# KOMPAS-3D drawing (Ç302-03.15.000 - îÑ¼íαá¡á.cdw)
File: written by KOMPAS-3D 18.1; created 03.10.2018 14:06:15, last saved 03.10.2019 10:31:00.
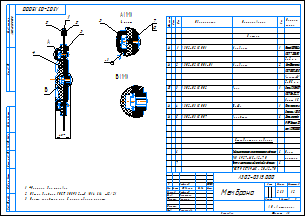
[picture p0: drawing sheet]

Sheet 1: A3, landscape

Document properties: Автор: Милов; Полное имя файла: D:\Мембранные насосы\Мембранный электропривод\А302-00.00.000 - ASTRA-302 (МЭ200)\Чертежи Полипропилен\А302-03.15.000 - Мембрана.cdw; Масса: 2.62614

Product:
- Part/product: (unnamed)
  - Component: Болт с шестигранной головкой с фланцем  / ГОСТ Р 55739-М5 x 20-A2-70  | pos. 7  | Раздел спецификации: Стандартные изделия
  - Component: Гайка шестигранная самостопорящаяся с фланцем / DIN 6927-M5-A2-70  | pos. 6  | Раздел спецификации: Стандартные изделия; Примечание: Нерж. / насечки
  - Component: Заглушка  | designation А302-03.15.007  | pos. 5  | Раздел спецификации: Детали; Форматы листов документа: А4; Примечание: Деталь заготовка  / FV PPR Заглушка @2~20 / арт. AA229020000
  - Component: Шайба  | designation А302-03.15.003  | pos. 4  | Раздел спецификации: Детали; Форматы листов документа: А4; Примечание: Полипропилен / Стержень @2~300
  - Component: Упор  | designation А302-02.15.002  | pos. 3  | Раздел спецификации: Детали; Форматы листов документа: А3; Примечание: Сталь 12Х18Н10Т / ГОСТ 5632-72 / Лист 15
  - Component: Мембрана  | designation А302-02.15.001-01  | pos. 2  | Раздел спецификации: Детали; Форматы листов документа: А4; Примечание: Лист Фторопласт-4 /  ГОСТ 10007-80 Е / "каленный" / S=0,5 мм
  - Component: Мембрана  | designation А302-02.15.001  | pos. 1  | Раздел спецификации: Детали; Форматы листов документа: А4; Примечание: Пластина ІФ-IІ ТМКЩ-C-4 / ГОСТ 7338-90 / S=2 мм

Title block, sheet 1: Наименование: Мембрана; designation: А302-03.15.000; Масса: 2,63; scale: 1:2; Количество листов документа: 1; organisation: АО «Астерион»; Форматы листов документа: A3; stored path: \\192.168.87.28\Konstructor_doc\Мембранные насосы\Мембранный электропривод\А302-00.00.000 - ASTRA-302 (МЭ200)\3Д ПВХ\А302-01.15.000 - Мембрана.cdw; Разработал: Лифлянд; Проверил: Борисенко; Т. контр.: Лучихин; Утвердил: Григорьева

Views: Вид 1, Местный разрез 1, Вид:2, Выносной элемент 3, Выносной элемент 4, Выносной элемент А, Выносной элемент, Выносной элемент Б
Referenced files in D:\Мембранные насосы\Мембранный электропривод\А302-00.00.000 - ASTRA-302 (МЭ200)\3Д ПВХ\: А302-01.15.001-01- Мембрана.m3d, А302-01.15.007 - Заглушка.m3d, А302-01.15.001 - Мембрана.m3d, А302-01.15.002 - Упор.a3d, А302-01.15.003 - Шайба.m3d, А302-01.15.000 - Мембрана.a3d, А302-01.15.001 - Мембрана.cdw, А302-01.15.002 - Упор.m3d, А302-01.15.008 - Кольцо плоское Ф4.m3d, А302-01.15.008 - Кольцо плоское уплотнительное 5-13-10 Ф4.cdw, А302-01.15.009 - Кольцо плоское Ф4.m3d, А302-01.15.007 - Заглушка.cdw, А302-01.15.011 - Заглушка резьбовая.m3d, А302-01.15.011 - Заглушка резьбовая.cdw
Referenced files in Z:\Мембранные насосы\Мембранный электропривод\А302-00.00.000 - ASTRA-302 (МЭ200)\3Д ПВХ\: А302-01.15.000 - Мембрана.a3d, А302-01.15.008 - Кольцо плоское Ф4.m3d
Referenced files in D:\2 Стандартные изделия 3D\Гайки\DIN 6927\: Гайка шестигранная самостопорящаяся с фланцем DIN 6927-M5 - A2-70.m3d
Referenced files in \\192.168.87.28\Konstructor_doc\Мембранные насосы\Мембранный электропривод\А302-00.00.000 - ASTRA-302 (МЭ200)\3Д ПВХ\: А302-01.15.011 - Заглушка резьбовая.cdw
Referenced files in D:\Мембранные насосы\Мембранный электропривод\А302-00.00.000 - ASTRA-302 (МЭ200)\Чертежи Полипропилен\: А302-02.15.002 - Упор.cdw
Referenced files in C:\Program Files\ASCON\KOMPAS-3D v18\Libs\PartLib\DATA\VAULT\methods\kompas\3d\: PLib_Bolt_1_ISO_1100.m3d, PLib_Nut_ISO_1100.m3d
Referenced files in C:\Program Files\ASCON\KOMPAS-3D V16\Libs\PartLib\DATA\vault\Methods\Kompas\3D\: PLib_Nut_ISO_1100.m3d, PLib_Bolt_1_ISO_1100.m3d
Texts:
  Шайба
  Упор
  Болт с шестигранной головкой с фланцем
  ГОСТ Р  55739-М5 x 25-A2-70
  ГОСТ
  Нерж.
  Нержавеющая сталь
  Гайка шестигранная самостопорящаяся с фланцем
  DIN 6927-M5-A2-70
  Гайка
  шестигранная
  самостопорящаяся
  фланцем
  DIN
  насечки
  Нерж. / насечки
  Кольцо плоское
  уплотнительное 5-13-10 Ф4
  Кольцо плоское  / уплотнительное 5-13-10 Ф4
  ГОСТ Р  55739-М8 x 30-A2-70
  Кольцо плоское Ф4
  Заглушка
  Заглушка резьбовая
  Лента ФУМ
  Лента
  ФУМ
  3D_Doc-graphic.lyt,1.000000-4294967295-203648116615
  Болт с шестигранной головкой с фланцем ГОСТ Р 55739-М5 x 20-A2-70
  Болт
  шестигранной
  головкой
  Пластина ІФ-IІ ТМКЩ-C-4
  ГОСТ 7338-90
  Пластина ІФ-IІ ТМКЩ-C-4 / ГОСТ 7338-90 / S=2 мм
  Лист Фторопласт-4
  ГОСТ 10007-80 Е
  "каленный"
  Лист Фторопласт-4 /  ГОСТ 10007-80 Е / "каленный" / S=0,5 мм
  Сталь 12Х18Н10Т
  ГОСТ 5632-72
  Лист 15
  Сталь 12Х18Н10Т / ГОСТ 5632-72 / Лист 15
  Полипропилен
  Стержень  300
  Полипропилен / Стержень @2~300
  Деталь заготовка
  FV PPR Заглушка  20
  арт. AA229020000
  Деталь заготовка  / FV PPR Заглушка @2~20 / арт. AA229020000
  ГОСТ Р 55739-М5 x 20-A2-70
  Гайка шестигранная с фланцем ГОСТ Р ИСО 4161 - M5 - A2-70
  Гайка шестигранная самостопорящаяся с фланцем / DIN 6927-M5-A2-70
  Болт с шестигранной головкой с фланцем ГОСТ Р 55739-М8 x 16-A2-70
Dimensions and other numbers on the sheet: 2; 1; 3; 4; 40; 6 мест; 5; 7; 8; 10; 9; 6; 11; 12; 100; 41; 48; 1:2; 2,63; 09.09.2019

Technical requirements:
  *Размеры для справок.
  Общие допуски ГОСТ 30893.2-mK (H14, h14,  t2/2).
  Паять заглушки поз. 5 после сборки пакета.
